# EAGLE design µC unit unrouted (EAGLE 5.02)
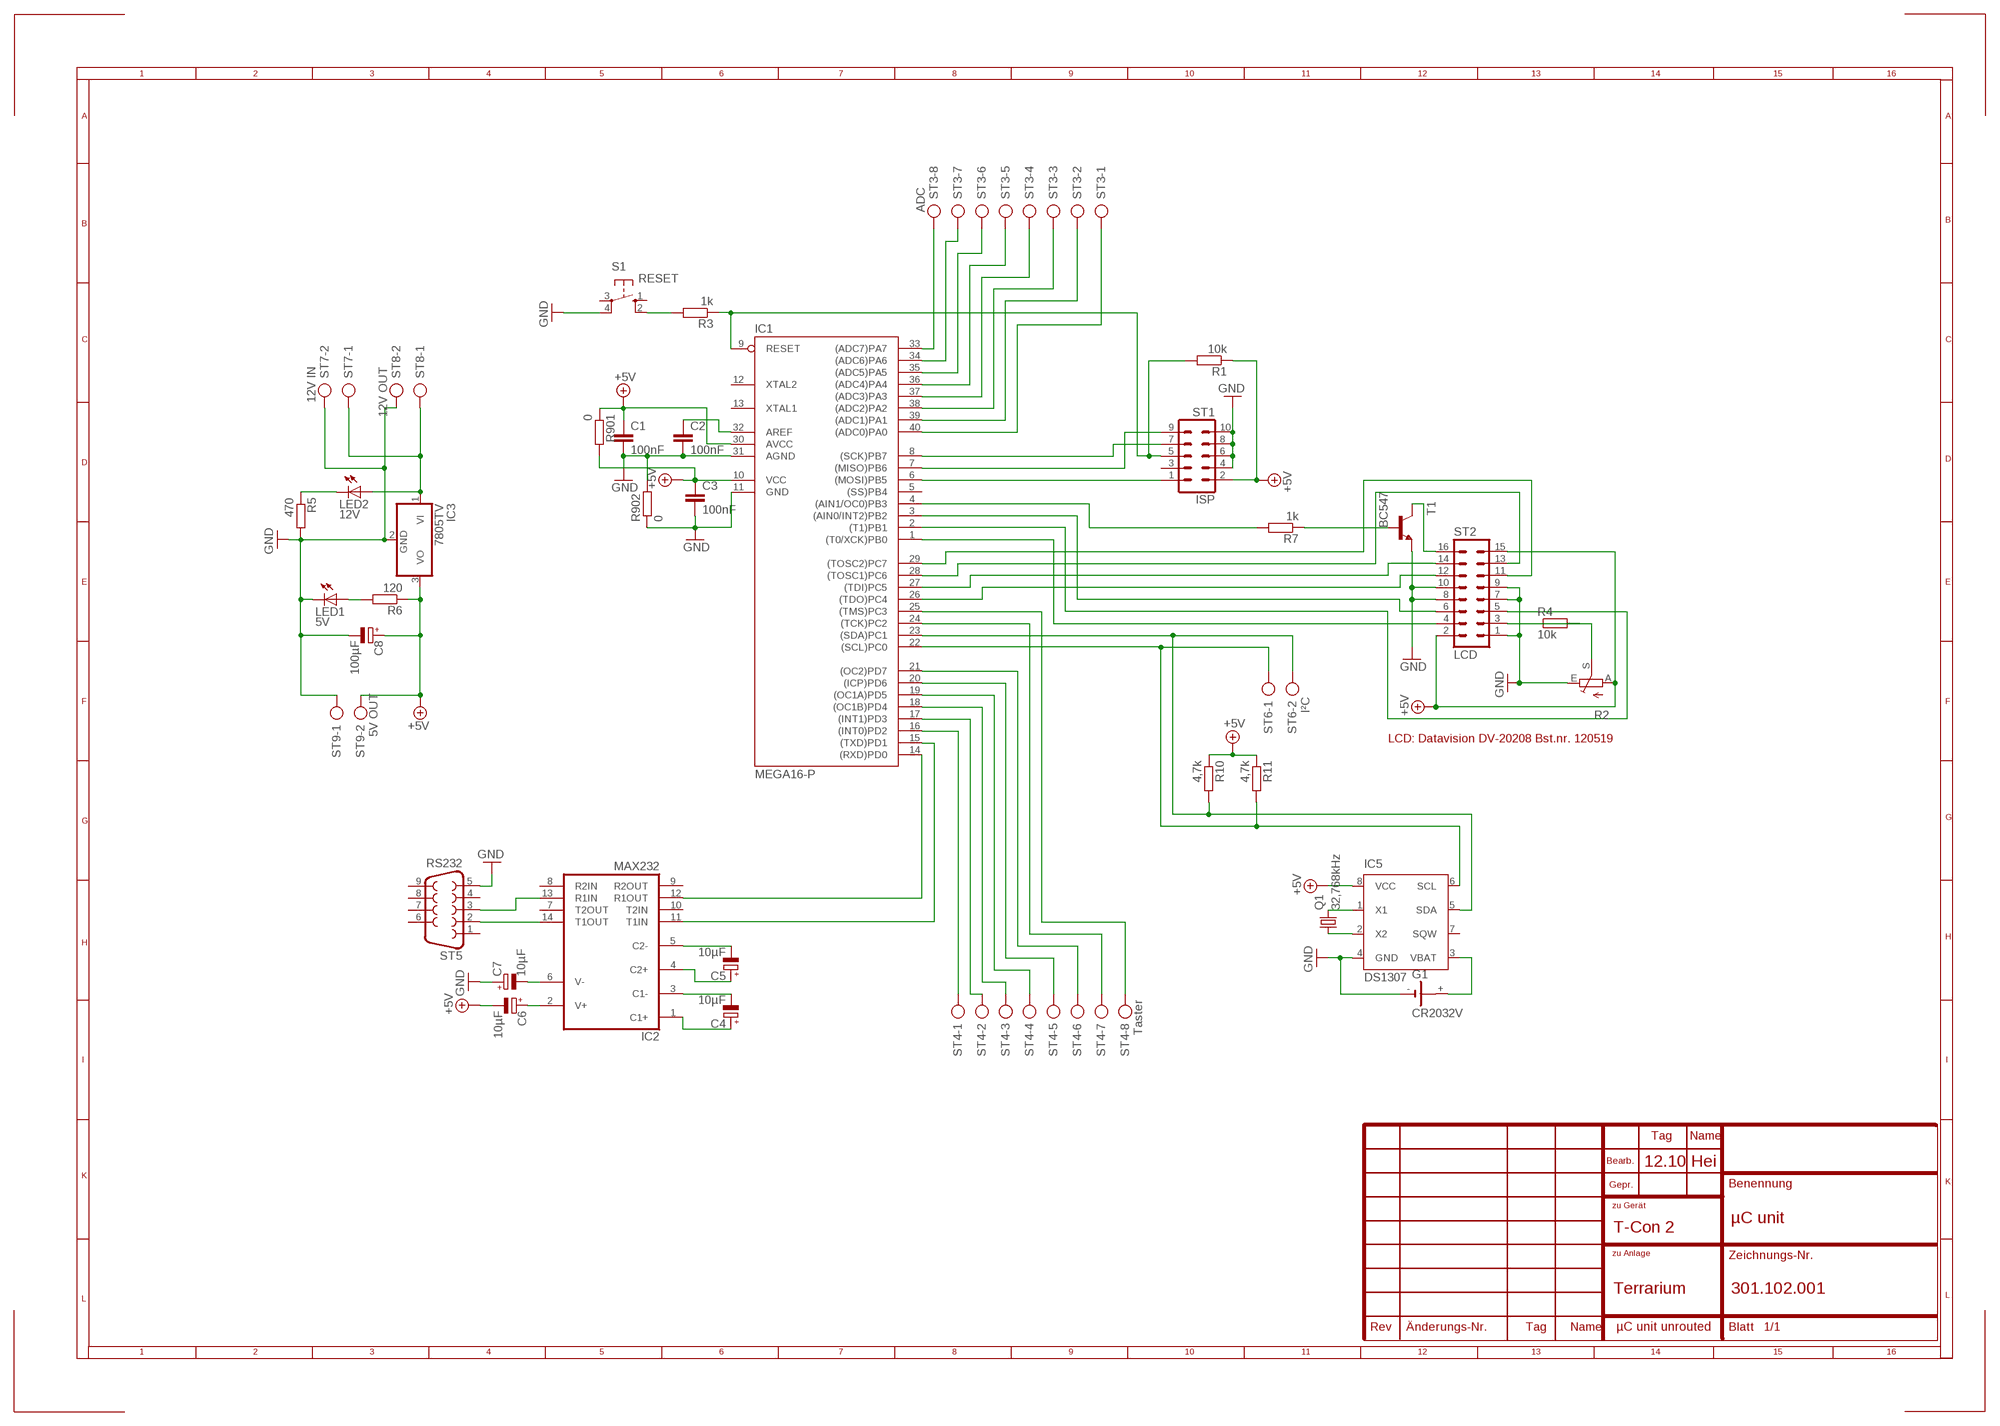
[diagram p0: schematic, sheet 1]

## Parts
C1  100nF  C-EU050-024X044  [C050-024X044]
C2  100nF  C-EU050-024X044  [C050-024X044]
C3  100nF  C-EU050-024X044  [C050-024X044]
C4  10µF  CPOL-EUE5-6  [E5-6]
C5  10µF  CPOL-EUE5-6  [E5-6]
C6  10µF  CPOL-EUE5-6  [E5-6]
C7  10µF  CPOL-EUE5-6  [E5-6]
C8  100µF  CPOL-EUE2.5-6  [E2,5-6]
G1  CR2032V  [CR2032V]
IC1  MEGA16-P  [DIL40]
IC2  MAX232  [DIL16]
IC3  7805TV  [TO220V]
IC5  DS1307  [DIL08]
LED1  5V  LED5MM  [LED5MM]
LED2  12V  LED5MM  [LED5MM]
Q1  32,768kHz  CRYSTALTC26H  [TC26H]
R1  10k  R-EU_0207/10  [0207/10]
R2  TRIM_EU-LI15  [LI15]
R3  1k  R-EU_0207/10  [0207/10]
R4  10k  R-EU_0207/2V  [0207/2V]
R5  470  R-EU_0207/10  [0207/10]
R6  120  R-EU_0207/10  [0207/10]
R7  1k  R-EU_0207/15  [0207/15]
R10  4,7k  R-EU_0207/10  [0207/10]
R11  4,7k  R-EU_0207/10  [0207/10]
R901  0  R-EU_0207/10  [0207/10]
R902  0  R-EU_0207/10  [0207/10]
S1  RESET  10-XX  [B3F-10XX]
ST1  ISP  MA05-2  [MA05-2]
ST2  LCD  MA08-2  [MA08-2]
ST3  ADC  AK500/8  [AK500/8]
ST4  Taster  AK500/8  [AK500/8]
ST5  RS232  F09HP  [F09HP]
ST6  I²C  AK500/2  [AK500/2]
ST7  12V IN  AK500/2  [AK500/2]
ST8  12V OUT  AK500/2  [AK500/2]
ST9  5V OUT  AK500/2  [AK500/2]
T1  BC547  BC547B-NPN-TO92-EBC  [TO92-EBC]

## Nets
+5V: C1.1 C3.1 C6.- C8.+ IC1.10(VCC) IC1.30(AVCC) IC3.3(VO) IC5.8(VCC) R1.1 R2.A R6.1 R10.1 R11.1 R901.1 R901.2 ST1.2 ST2.2 ST2.15 ST9.2
GND: C1.2 C2.2 C3.2 C7.+ C8.- G1.- IC1.11(GND) IC1.31(AGND) IC3.2(GND) IC5.4(GND) LED1.K(C) R2.E R5.2 R902.1 R902.2 S1.4(P1) ST1.4 ST1.6 ST1.8 ST1.10 ST2.1 ST2.7 ST2.8 ST2.9 ST2.10 ST5.5 ST7.2 ST8.2 ST9.1 T1.E
N$1: C5.+ IC2.4(C2+)
N$2: C6.+ IC2.2(V+)
N$3: G1.+ IC5.3(VBAT)
N$4: IC1.6((MOSI)PB5) ST1.1
N$5: IC1.9(RESET) R1.2 R3.1 ST1.5
N$6: IC1.7((MISO)PB6) ST1.9
N$7: IC1.8((SCK)PB7) ST1.7
N$8: IC1.24((TCK)PC2) ST4.7
N$9: C2.1 IC1.32(AREF)
N$10: IC1.16((INT0)PD2) ST4.1
N$11: IC5.2(X2) Q1.1
N$12: IC5.1(X1) Q1.2
N$13: IC1.17((INT1)PD3) ST4.2
N$14: IC1.22((SCL)PC0) IC5.6(SCL) R11.2 ST6.1
N$15: IC1.18((OC1B)PD4) ST4.3
N$16: IC1.14((RXD)PD0) IC2.12(R1OUT)
N$17: C7.- IC2.6(V-)
N$18: R3.2 S1.2(S1)
N$19: IC1.34((ADC6)PA6) ST3.7
N$20: IC1.33((ADC7)PA7) ST3.8
N$21: IC1.35((ADC5)PA5) ST3.6
N$22: IC1.36((ADC4)PA4) ST3.5
N$23: IC1.37((ADC3)PA3) ST3.4
N$24: C5.- IC2.5(C2-)
N$25: C4.- IC2.3(C1-)
N$26: C4.+ IC2.1(C1+)
N$27: IC2.13(R1IN) ST5.3
N$28: IC1.15((TXD)PD1) IC2.11(T1IN)
N$29: IC2.14(T1OUT) ST5.2
N$30: IC1.38((ADC2)PA2) ST3.3
N$31: IC1.39((ADC1)PA1) ST3.2
N$32: IC1.40((ADC0)PA0) ST3.1
N$33: R4.2 ST2.3
N$34: IC1.29((TOSC2)PC7) ST2.11
N$35: IC1.1((T0/XCK)PB0) ST2.4
N$36: IC1.2((T1)PB1) ST2.5
N$37: IC1.3((AIN0/INT2)PB2) ST2.6
N$38: ST2.16 T1.C
N$39: IC1.23((SDA)PC1) IC5.5(SDA) R10.2 ST6.2
N$40: IC3.1(VI) LED2.A ST7.1 ST8.1
N$41: IC1.26((TDO)PC4) ST2.12
N$42: IC1.27((TDI)PC5) ST2.14
N$43: IC1.28((TOSC1)PC6) ST2.13
N$44: IC1.4((AIN1/OC0)PB3) R7.2
N$45: IC1.19((OC1A)PD5) ST4.4
N$46: IC1.20((ICP)PD6) ST4.5
N$47: IC1.21((OC2)PD7) ST4.6
N$48: IC1.25((TMS)PC3) ST4.8
N$49: R2.S R4.1
N$50: LED1.A R6.2
N$51: LED2.K(C) R5.1
N$52: R7.1 T1.B
Unconnected: G1.+@1(+) IC1.5((SS)PB4) IC1.12(XTAL2) IC1.13(XTAL1) IC2.7(T2OUT) IC2.8(R2IN) IC2.9(R2OUT) IC2.10(T2IN) IC5.7(SQW) S1.1(S) S1.3(P) ST1.3 ST5.1 ST5.4 ST5.6 ST5.7 ST5.8 ST5.9

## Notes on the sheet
- LCD: Datavision DV-20208 Bst.nr. 120519
- 12.10 | Hei
- µC unit
- T-Con 2
- Terrarium | 301.102.001

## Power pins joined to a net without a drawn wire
GND: IC2.15(GND)
VCC: IC2.16(VCC)

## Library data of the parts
C1-C3 = rcl:C-EU: CAPACITOR, European symbol
C4-C8 = rcl:CPOL-EU: POLARIZED CAPACITOR, European symbol
G1 = battery:CR2032V: LI BATTERY Varta
IC1 = atmel:MEGA16-P: MICROCONTROLLER 16 Kbytes FLASH 1 kbytes SRAM 512 bytes EEPROM USART 8-channel 10 bit ADC Source: avr.lbr
IC2 = maxim:MAX232: RS232 TRANSEIVER
IC3 = linear:78*: Positive VOLTAGE REGULATOR Source: http://cache.national.com/ds/LM/LM78L05.pdf http://www.fairchildsemi.com/ds/LM/LM7805.pdf
IC5 = ds1307_pcf8583:DS1307: I2C-Bus CLOCK/CALENDAR
LED1 LED2 = led:LED: LED
Q1 = crystal:CRYSTAL: CRYSTAL
R1 R3-R7 R10 R11 R901 R902 = rcl:R-EU_: RESISTOR, European symbol
R2 = pot:TRIM_EU-: POTENTIOMETER
S1 = switch-omron:10-XX: OMRON SWITCH
ST1 = con-lstb:MA05-2: PIN HEADER
ST2 = con-lstb:MA08-2: PIN HEADER
ST3 ST4 = con-ptr500:AK500/8: CONNECTOR
ST5 = con-subd:F09: SUB-D
ST6-ST9 = con-ptr500:AK500/2: CONNECTOR
T1 = transistor:*-NPN-: NPN Transistror BF959 corrected 2008.03.06

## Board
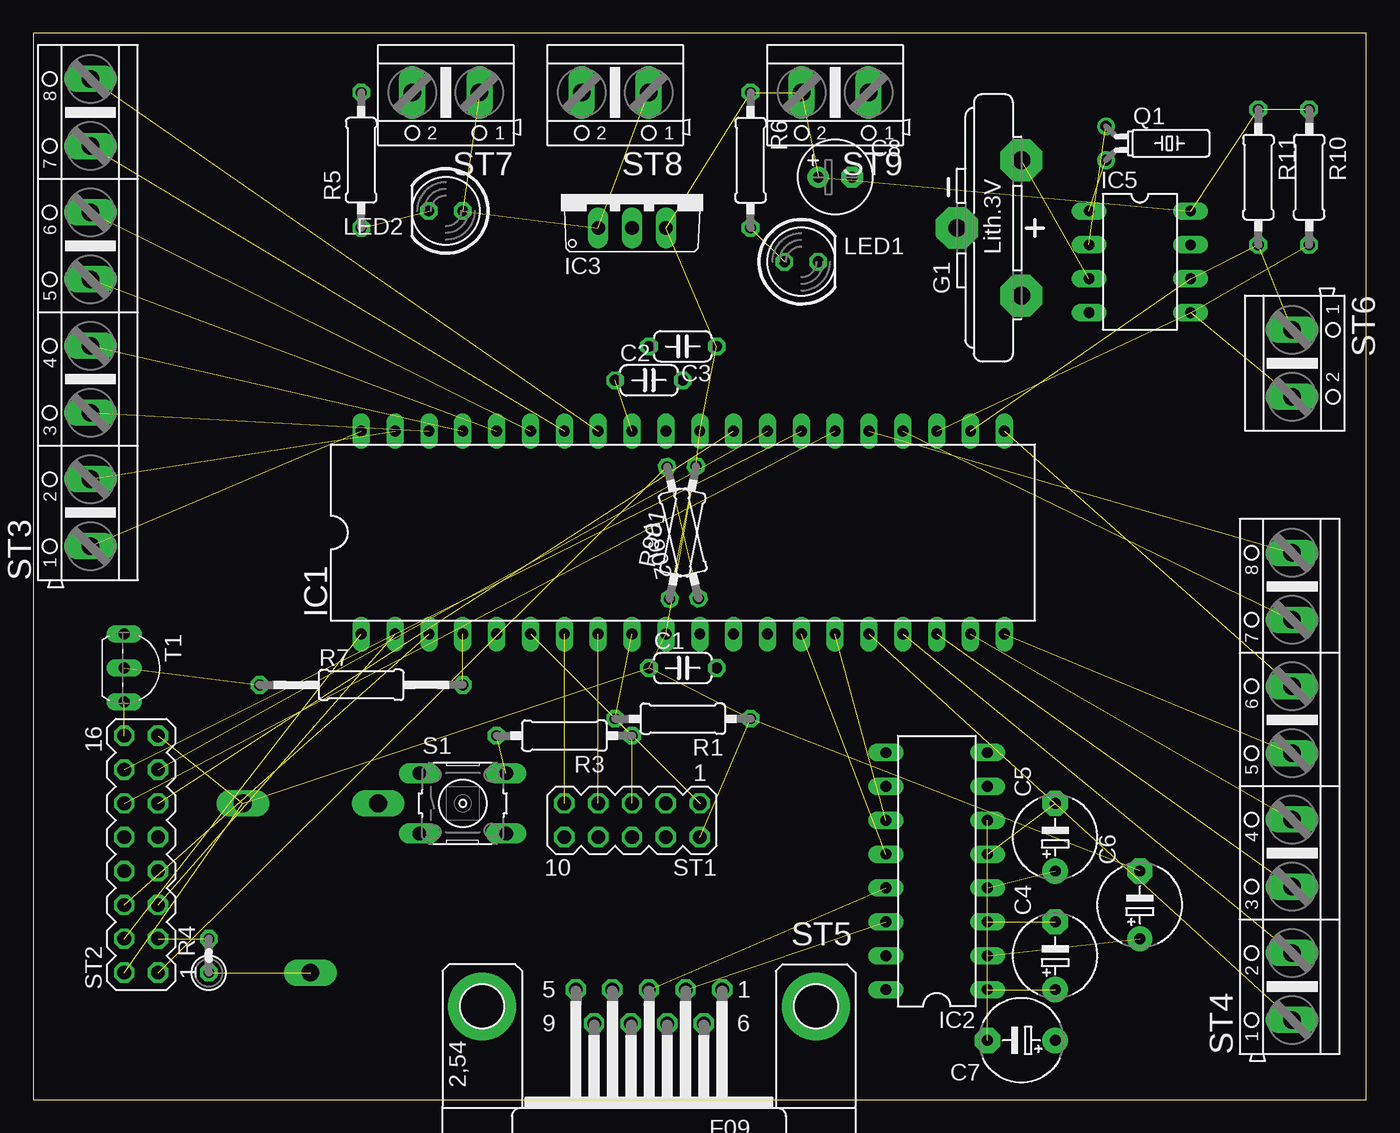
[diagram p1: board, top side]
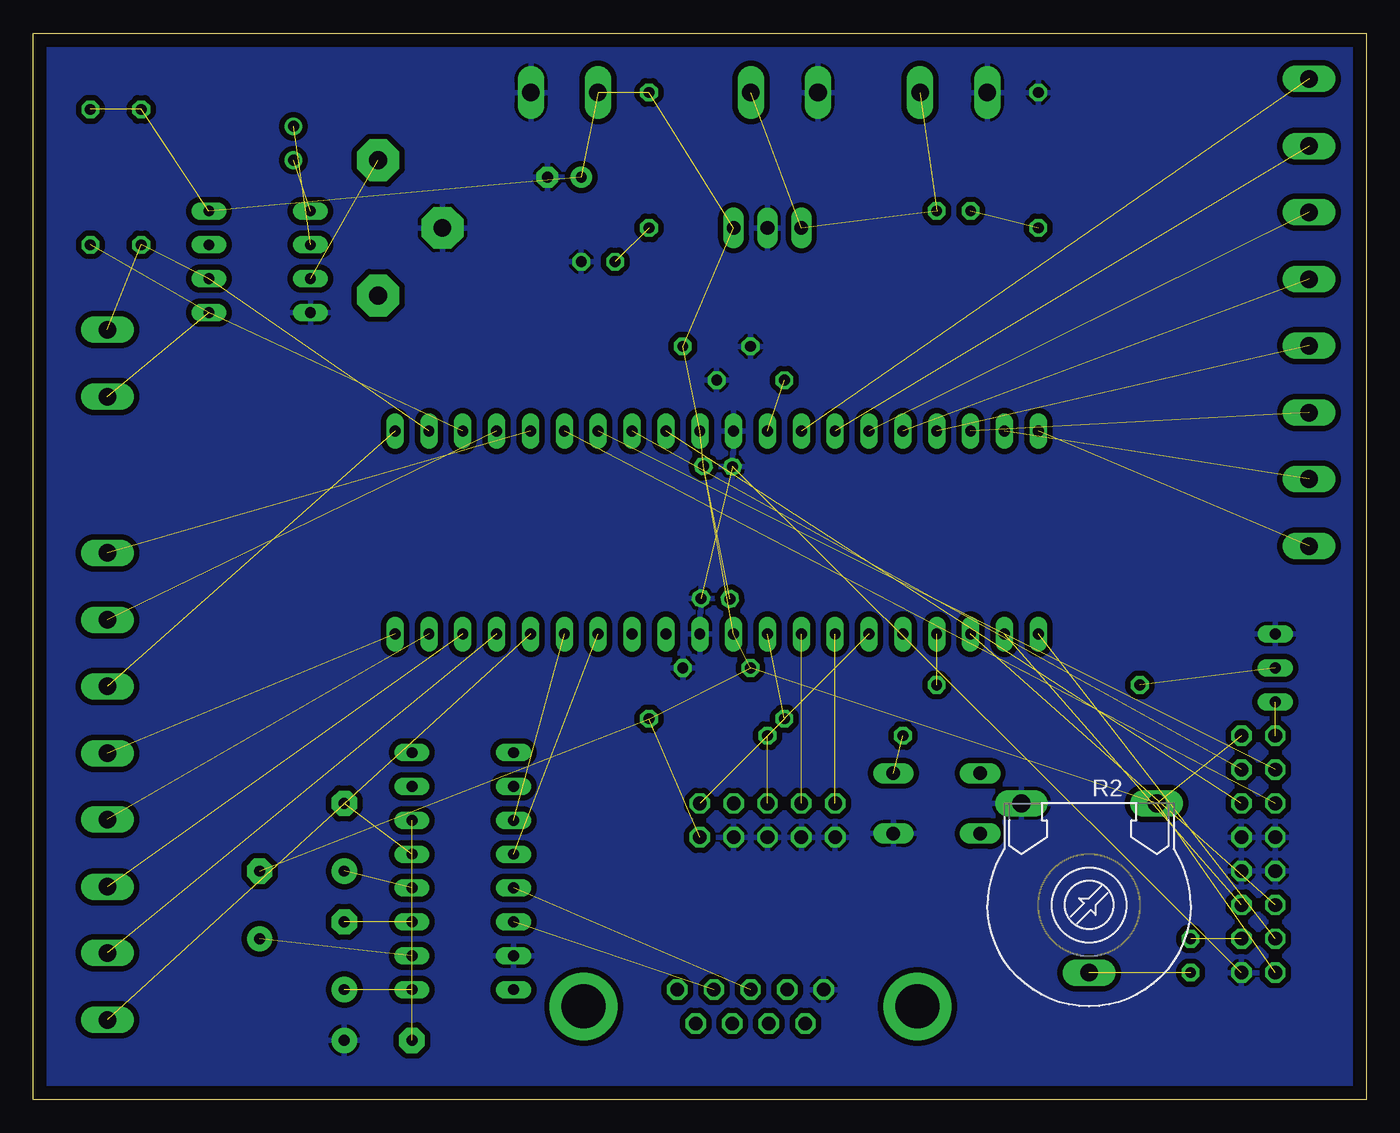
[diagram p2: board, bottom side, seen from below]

Size 100 x 80 mm. Coordinates in mm from the lower left corner, seen from the top.
Outline: 0,0 100,0 100,80 0,80 0,0
Copper layers (1*16): Top 0.035mm / dielectric 1.5mm / Bottom 0.035mm
Design rules "default": minimum track width 10mil, minimum drill 24mil, track to track 8mil, track to pad 8mil, pad to pad 8mil, via to via 8mil, smd to smd 8mil, copper to edge 40mil, drill to drill 8mil, minimum pad ring 10mil, minimum via ring 8mil, stop-mask expansion 4mil, vias tented up to drill 0mil, thermal gap 10mil
tRestrict: area 0.5,0.6 to 99.5,79.4

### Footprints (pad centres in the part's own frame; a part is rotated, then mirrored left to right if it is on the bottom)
C050-024X044 = drill 0.813 octagon: 1 -2.54,0; 2 2.54,0
E5-6 = drill 0.813 pad 1.905 round: + -2.54,0 | drill 0.813 pad 1.905 octagon: - 2.54,0
E2,5-6 = drill 0.813 pad 1.6 round: + -1.27,0 | drill 0.813 pad 1.6 octagon: - 1.27,0
CR2032V = drill 1.321 pad 3.15 octagon: + -2.54,-5.08; +@1 -2.54,5.08; - 2.286,0
DIL40 = drill 0.813 long: 1 -24.13,-7.62; 2 -21.59,-7.62; 3 -19.05,-7.62; 4 -16.51,-7.62; 5 -13.97,-7.62; 6 -11.43,-7.62; 7 -8.89,-7.62; 8 -6.35,-7.62; 9 -3.81,-7.62; 10 -1.27,-7.62; 11 1.27,-7.62; 12 3.81,-7.62; 13 6.35,-7.62; 14 8.89,-7.62; 15 11.43,-7.62; 16 13.97,-7.62; 17 16.51,-7.62; 18 19.05,-7.62; 19 21.59,-7.62; 20 24.13,-7.62; 21 24.13,7.62; 22 21.59,7.62; 23 19.05,7.62; 24 16.51,7.62; 25 13.97,7.62; 26 11.43,7.62; 27 8.89,7.62; 28 6.35,7.62; 29 3.81,7.62; 30 1.27,7.62; 31 -1.27,7.62; 32 -3.81,7.62; 33 -6.35,7.62; 34 -8.89,7.62; 35 -11.43,7.62; 36 -13.97,7.62; 37 -16.51,7.62; 38 -19.05,7.62; 39 -21.59,7.62; 40 -24.13,7.62
DIL16 = drill 0.813 long: 1 -8.89,-3.81; 2 -6.35,-3.81; 3 -3.81,-3.81; 4 -1.27,-3.81; 5 1.27,-3.81; 6 3.81,-3.81; 7 6.35,-3.81; 8 8.89,-3.81; 9 8.89,3.81; 10 6.35,3.81; 11 3.81,3.81; 12 1.27,3.81; 13 -1.27,3.81; 14 -3.81,3.81; 15 -6.35,3.81; 16 -8.89,3.81
TO220V = drill 1.016 long: 1 -2.54,-2.54; 2 0,-2.54; 3 2.54,-2.54
DIL08 = drill 0.813 long: 1 -3.81,-3.81; 2 -1.27,-3.81; 3 1.27,-3.81; 4 3.81,-3.81; 5 3.81,3.81; 6 1.27,3.81; 7 -1.27,3.81; 8 -3.81,3.81
LED5MM = drill 0.813 octagon: A -1.27,0; K 1.27,0
TC26H = drill 0.813 round: 1 -1.27,0; 2 1.27,0
0207/10 = drill 0.813 octagon: 1 -5.08,0; 2 5.08,0
LI15 = drill 1.321 long: A -5.08,-7.62; E 5.08,-7.62; S 0,5.08
0207/2V = drill 0.813 octagon: 1 -1.27,0; 2 1.27,0
0207/15 = drill 0.813 octagon: 1 -7.62,0; 2 7.62,0
B3F-10XX = drill 1.016 long: 1 -3.251,2.261; 2 3.251,2.261; 3 -3.251,-2.261; 4 3.251,-2.261
MA05-2 = drill 1.016 octagon: 1 -5.08,-1.27; 2 -5.08,1.27; 3 -2.54,-1.27; 4 -2.54,1.27; 5 0,-1.27; 6 0,1.27; 7 2.54,-1.27; 8 2.54,1.27; 9 5.08,-1.27; 10 5.08,1.27
MA08-2 = drill 1.016 octagon: 1 -8.89,-1.27; 2 -8.89,1.27; 3 -6.35,-1.27; 4 -6.35,1.27; 5 -3.81,-1.27; 6 -3.81,1.27; 7 -1.27,-1.27; 8 -1.27,1.27; 9 1.27,-1.27; 10 1.27,1.27; 11 3.81,-1.27; 12 3.81,1.27; 13 6.35,-1.27; 14 6.35,1.27; 15 8.89,-1.27; 16 8.89,1.27
AK500/8 = drill 1.321 long: 1 -17.526,0; 2 -12.497,0; 3 -7.518,0; 4 -2.489,0; 5 2.489,0; 6 7.518,0; 7 12.497,0; 8 17.526,0
F09HP = drill 1.016 octagon: 1 -5.486,-1.27; 2 -2.743,-1.27; 3 0,-1.27; 4 2.743,-1.27; 5 5.486,-1.27; 6 -4.115,1.27; 7 -1.372,1.27; 8 1.372,1.27; 9 4.115,1.27 | drill 3.302 pad 5.08 round: G1 -12.522,0; G2 12.522,0
AK500/2 = drill 1.321 long: 1 -2.515,0; 2 2.515,0
TO92-EBC = drill 0.813 long: B 0,-1.27; C 2.54,-1.27; E -2.54,-1.27

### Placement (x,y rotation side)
C1  48.73,32.38 0 top
C2  46.19,53.97 0 top
C3  48.73,56.51 180 top
C4  76.67,10.79 90 top
C5  76.67,19.68 90 top
C6  83.02,14.6 90 top
C7  74.13,4.44 180 top
C8  60.16,69.21 0 top
G1  71.59,65.4 180 top
IC1  48.73,42.54 0 top
IC2  67.78,17.14 90 top
IC3  44.92,67.94 0 top
IC5  83.02,62.86 270 top
LED1  57.62,62.86 0 top
LED2  30.95,66.67 180 top
Q1  80.48,71.75 270 top
R1  48.73,28.57 180 top
R2  20.79,14.6 180 bottom
R3  39.84,27.3 180 top
R4  13.17,10.79 90 top
R5  24.6,70.48 90 top
R6  53.81,70.48 270 top
R7  24.6,31.11 0 top
R10  95.72,69.21 270 top
R11  91.91,69.21 270 top
R901  48.73,42.54 78.8 top
R902  48.73,42.54 103.5 top
S1  32.22,22.22 0 top
ST1  44.92,20.95 180 top
ST2  8.09,18.41 90 top
ST3  4.28,59.05 90 top
ST4  94.45,23.49 90 top
ST5  46.19,6.98 180 top
ST6  94.45,55.24 270 top
ST7  30.95,75.56 180 top
ST8  43.65,75.56 180 top
ST9  60.16,75.56 180 top
T1  8.09,32.38 270 top

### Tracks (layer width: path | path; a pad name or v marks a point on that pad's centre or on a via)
+5V  (18 unrouted)
GND  (2 unrouted)
  pour Bottom (isolate 0.406): 0.47,79.37 99.53,79.37 99.53,0.63 0.47,0.63
N$1  (1 unrouted)
N$2  (1 unrouted)
N$3  (1 unrouted)
N$4  (1 unrouted)
N$5  (3 unrouted)
N$6  (1 unrouted)
N$7  (1 unrouted)
N$8  (1 unrouted)
N$9  (1 unrouted)
N$10  (1 unrouted)
N$11  (1 unrouted)
N$12  (1 unrouted)
N$13  (1 unrouted)
N$14  (3 unrouted)
N$15  (1 unrouted)
N$16  (1 unrouted)
N$17  (1 unrouted)
N$18  (1 unrouted)
N$19  (1 unrouted)
N$20  (1 unrouted)
N$21  (1 unrouted)
N$22  (1 unrouted)
N$23  (1 unrouted)
N$24  (1 unrouted)
N$25  (1 unrouted)
N$26  (1 unrouted)
N$27  (1 unrouted)
N$28  (1 unrouted)
N$29  (1 unrouted)
N$30  (1 unrouted)
N$31  (1 unrouted)
N$32  (1 unrouted)
N$33  (1 unrouted)
N$34  (1 unrouted)
N$35  (1 unrouted)
N$36  (1 unrouted)
N$37  (1 unrouted)
N$38  (1 unrouted)
N$39  (3 unrouted)
N$40  (3 unrouted)
N$41  (1 unrouted)
N$42  (1 unrouted)
N$43  (1 unrouted)
N$44  (1 unrouted)
N$45  (1 unrouted)
N$46  (1 unrouted)
N$47  (1 unrouted)
N$48  (1 unrouted)
N$49  (1 unrouted)
N$50  (1 unrouted)
N$51  (1 unrouted)
N$52  (1 unrouted)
